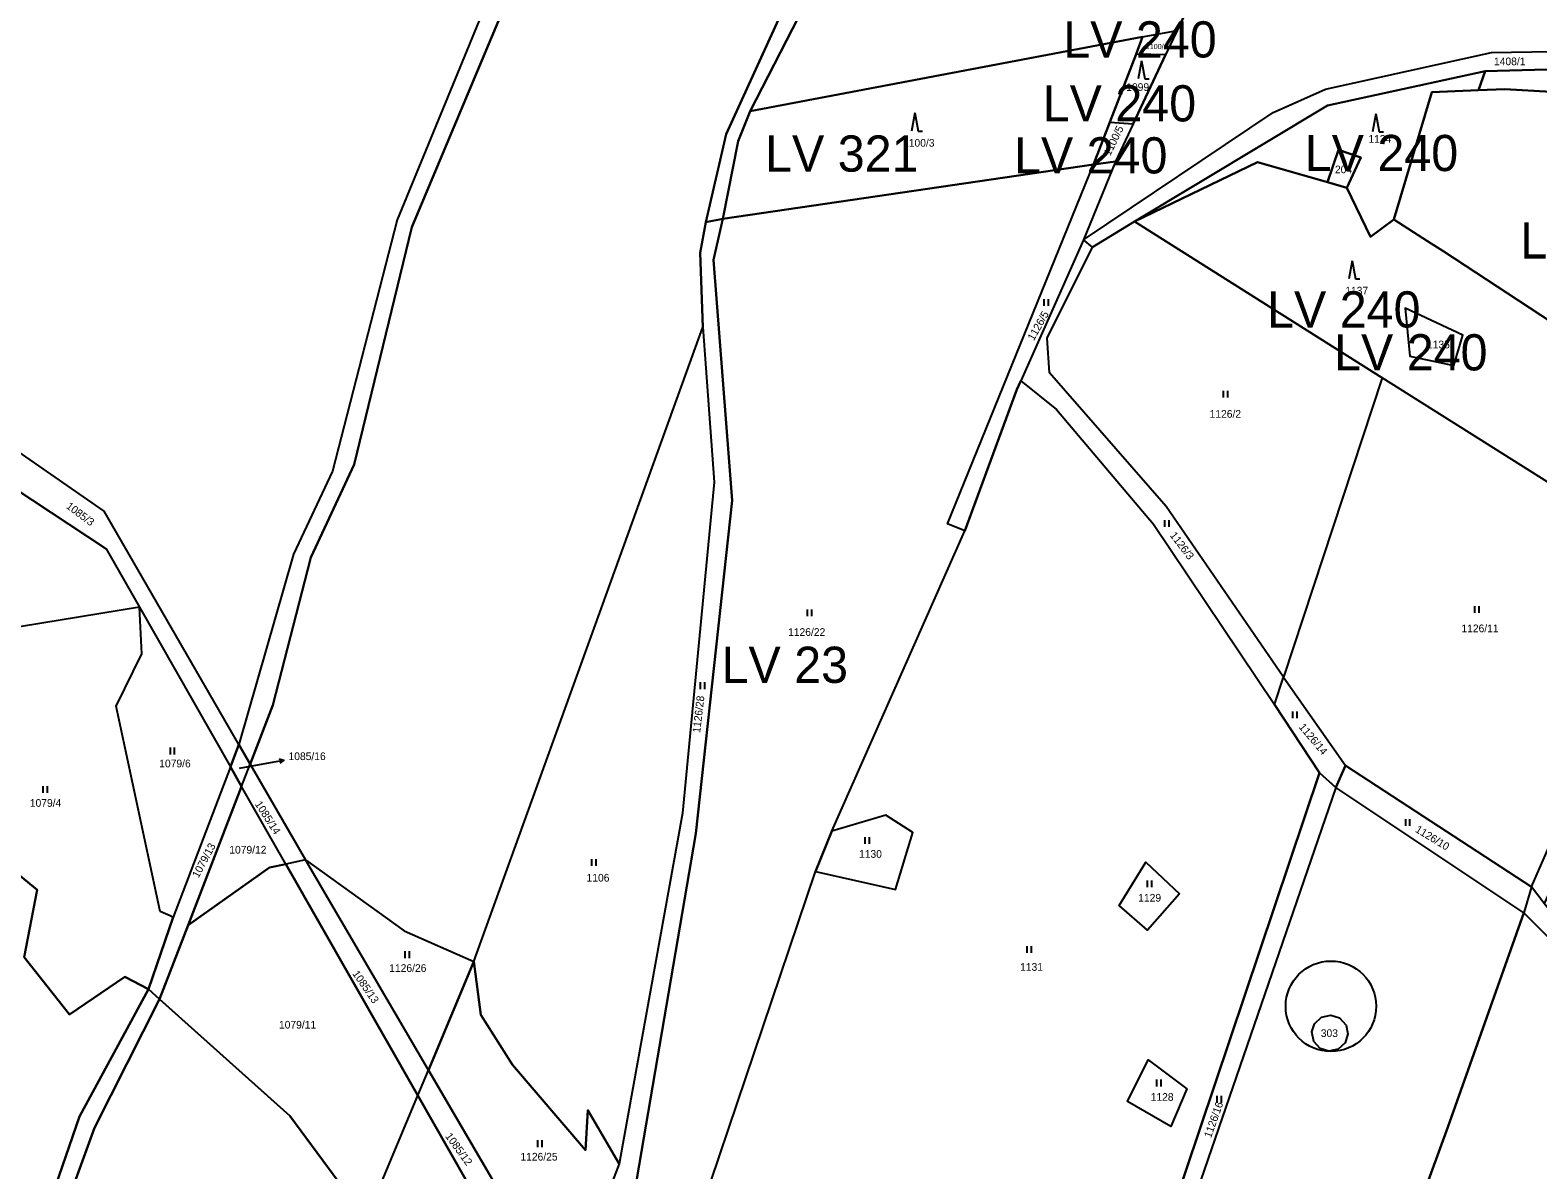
# Model space of a CAD drawing. Extents: x -588699 to -585793, y -1060280 to -1056731.
# Drawn here: x -587820.9 to -587487.8, y -1059020.2 to -1058768.4 of the extents above; entities that cross this region are included whole.
import ezdxf

# ---------------------------------------------------------------- set-up
doc = ezdxf.new("R2010")
doc.units = 0
for name, color, linetype in [('Druh pozemku', 7, 'Continuous'), ('Neřešené', 7, 'Continuous'), ('Parcela nároku', 7, 'Continuous'), ('Parcelní číslo', 7, 'Continuous'), ('Stavby', 7, 'Continuous'), ('Vnější obvod_převzatý', 7, 'Continuous')]:
    doc.layers.add(name, color=color, linetype=linetype)

msp = doc.modelspace()

# ---------------------------------------------------------------- linework, layer by layer
at = {"layer": 'Druh pozemku'}
for p, q in [((-587575.37, -1058775.14), (-587576.1, -1058779.14)), ((-587575.37, -1058775.14), (-587574.64, -1058779.14)), ((-587574.64, -1058779.14), (-587573.64, -1058779.14)), ((-587625.45, -1058786.65), (-587626.19, -1058790.65)), ((-587625.45, -1058786.65), (-587624.72, -1058790.65)), ((-587523.58, -1058786.82), (-587524.32, -1058790.82)), ((-587523.58, -1058786.82), (-587522.85, -1058790.82)), ((-587624.72, -1058790.65), (-587623.72, -1058790.65)), ((-587522.85, -1058790.82), (-587521.85, -1058790.82)), ((-587528.79, -1058819.3), (-587529.53, -1058823.3)), ((-587528.79, -1058819.3), (-587528.06, -1058823.3)), ((-587528.06, -1058823.3), (-587527.06, -1058823.3)), ((-587596.92, -1058827.76), (-587596.92, -1058829.26)), ((-587595.9, -1058829.26), (-587595.9, -1058827.76)), ((-587557.31, -1058848.04), (-587557.31, -1058849.54)), ((-587556.29, -1058849.54), (-587556.29, -1058848.04)), ((-587570.26, -1058876.6), (-587570.26, -1058878.1)), ((-587569.23, -1058878.1), (-587569.23, -1058876.6)), ((-587649.26, -1058896.35), (-587649.26, -1058897.85)), ((-587648.23, -1058897.85), (-587648.23, -1058896.35)), ((-587501.76, -1058895.62), (-587501.76, -1058897.12)), ((-587500.73, -1058897.12), (-587500.73, -1058895.62)), ((-587672.87, -1058912.44), (-587672.87, -1058913.94)), ((-587671.84, -1058913.94), (-587671.84, -1058912.44)), ((-587541.97, -1058918.91), (-587541.97, -1058920.41)), ((-587540.95, -1058920.41), (-587540.95, -1058918.91)), ((-587790.04, -1058926.89), (-587790.04, -1058928.39)), ((-587789.02, -1058928.39), (-587789.02, -1058926.89)), ((-587818.16, -1058935.4), (-587818.16, -1058936.9)), ((-587817.14, -1058936.9), (-587817.14, -1058935.4)), ((-587517.03, -1058942.67), (-587517.03, -1058944.17)), ((-587516.01, -1058944.17), (-587516.01, -1058942.67)), ((-587636.5, -1058946.64), (-587636.5, -1058948.14)), ((-587635.47, -1058948.14), (-587635.47, -1058946.64)), ((-587696.91, -1058951.53), (-587696.91, -1058953.03)), ((-587695.89, -1058953.03), (-587695.89, -1058951.53)), ((-587574.06, -1058956.22), (-587574.06, -1058957.72)), ((-587573.04, -1058957.72), (-587573.04, -1058956.22)), ((-587738.11, -1058971.88), (-587738.11, -1058973.38)), ((-587737.08, -1058973.38), (-587737.08, -1058971.88)), ((-587600.69, -1058970.74), (-587600.69, -1058972.24)), ((-587599.67, -1058972.24), (-587599.67, -1058970.74)), ((-587572.05, -1059000.24), (-587572.05, -1059001.74)), ((-587571.03, -1059001.74), (-587571.03, -1059000.24)), ((-587558.69, -1059003.84), (-587558.69, -1059005.34)), ((-587557.67, -1059005.34), (-587557.67, -1059003.84)), ((-587708.85, -1059013.64), (-587708.85, -1059015.14)), ((-587707.83, -1059015.14), (-587707.83, -1059013.64))]:
    msp.add_line(p, q, dxfattribs=at)
at = {"layer": 'Neřešené'}
msp.add_lwpolyline([(-587534.2, -1058801.97), (-587531.78, -1058794.81), (-587526.9, -1058796.47), (-587529.95, -1058803.18)], close=True, dxfattribs=at)
at = {"layer": 'Parcela nároku'}
for points in [[(-587647.07, -1058584.65), (-587664.66, -1058630.41), (-587683.23, -1058681.65), (-587693.72, -1058708.15), (-587714.84, -1058741.98), (-587721.68, -1058766.23), (-587739.86, -1058810.23), (-587754.13, -1058865.77), (-587762.73, -1058884.15), (-587774.83, -1058926.17), (-587772.32, -1058930.52), (-587767.29, -1058917.5), (-587758.89, -1058884.84), (-587749.31, -1058864.31), (-587736.6, -1058811.9), (-587717.44, -1058766.33), (-587711.58, -1058744.43), (-587689.88, -1058709.42), (-587678.89, -1058682.31), (-587662.12, -1058634.33), (-587639.34, -1058576.72)], [(-587639.34, -1058576.72), (-587662.12, -1058634.33), (-587678.89, -1058682.31), (-587689.88, -1058709.42), (-587711.58, -1058744.43), (-587717.44, -1058766.33), (-587736.6, -1058811.9), (-587749.31, -1058864.31), (-587758.89, -1058884.84), (-587767.29, -1058917.5), (-587772.32, -1058930.52), (-587760.08, -1058951.7), (-587738.27, -1058967.37), (-587722.9, -1058974.18), (-587672.29, -1058833.97), (-587672.88, -1058817.55), (-587671.61, -1058810.76), (-587667.13, -1058791.3), (-587654.74, -1058764.24), (-587629.6, -1058673.78), (-587614.6, -1058629.4), (-587607.6, -1058620.46), (-587591.67, -1058612.59)], [(-587647.07, -1058584.65), (-587664.66, -1058630.41), (-587683.23, -1058681.65), (-587693.72, -1058708.15), (-587714.84, -1058741.98), (-587721.68, -1058766.23), (-587739.86, -1058810.23), (-587754.13, -1058865.77), (-587762.73, -1058884.15), (-587774.83, -1058926.17), (-587804.58, -1058874.64), (-587847.22, -1058845.13)], [(-587591.67, -1058612.59), (-587607.6, -1058620.46), (-587614.6, -1058629.4), (-587629.6, -1058673.78), (-587654.74, -1058764.24), (-587667.13, -1058791.3), (-587671.61, -1058810.76), (-587667.89, -1058810.04), (-587664.46, -1058792.89), (-587661.81, -1058786.25), (-587651.11, -1058765.46), (-587635.03, -1058707.54), (-587611.6, -1058632.08), (-587605.95, -1058623.77), (-587550, -1058596.19)], [(-587503.55, -1058608.11), (-587519.89, -1058645.26), (-587523.16, -1058658.51), (-587545.16, -1058714.72), (-587549.47, -1058725.55), (-587557.48, -1058747.69), (-587567.46, -1058768.42), (-587570.01, -1058773.83), (-587577.2, -1058789.07), (-587581.11, -1058797.35), (-587588.18, -1058814.68), (-587546.21, -1058786.56), (-587534.66, -1058781.41), (-587498.02, -1058773.26), (-587471.36, -1058772.88)], [(-587518.99, -1059041.82), (-587507.67, -1059010.75), (-587490.84, -1058963.37), (-587532.39, -1058935.68), (-587573.18, -1059054.28)]]:
    msp.add_lwpolyline(points, dxfattribs=at)
for points in [[(-587555.44, -1058720.83), (-587567.98, -1058710.91), (-587568.51, -1058703.4), (-587557.67, -1058698.35), (-587557.12, -1058684.85), (-587563.12, -1058678.39), (-587554.81, -1058665.52), (-587552.28, -1058648.34), (-587544.06, -1058615.74), (-587541.88, -1058597.15), (-587538.61, -1058587.55), (-587540.61, -1058586.85), (-587550, -1058596.19), (-587605.95, -1058623.77), (-587611.6, -1058632.08), (-587635.03, -1058707.54), (-587651.11, -1058765.46), (-587661.81, -1058786.25), (-587575.09, -1058769.86), (-587567.46, -1058768.42), (-587557.48, -1058747.69), (-587549.47, -1058725.55)], [(-587575.09, -1058769.86), (-587567.46, -1058768.42), (-587570.01, -1058773.83), (-587576.54, -1058773.63)], [(-587664.46, -1058792.89), (-587667.89, -1058810.04), (-587585.95, -1058798.06), (-587582.34, -1058788.68), (-587576.54, -1058773.63), (-587575.09, -1058769.86), (-587661.81, -1058786.25)], [(-587498.02, -1058773.26), (-587471.36, -1058772.88), (-587419.8, -1058789.18), (-587416.34, -1058790.27), (-587417.7, -1058793.2), (-587474.82, -1058776.74), (-587499.41, -1058777.39), (-587534.25, -1058785.03), (-587576.88, -1058810.62), (-587586.16, -1058816.34), (-587588.18, -1058814.68), (-587546.21, -1058786.56), (-587534.66, -1058781.41)], [(-587570.01, -1058773.83), (-587576.54, -1058773.63), (-587582.34, -1058788.68), (-587577.2, -1058789.07)], [(-587529.95, -1058803.18), (-587526.9, -1058796.47), (-587531.78, -1058794.81), (-587534.2, -1058801.97), (-587549.72, -1058797.54), (-587576.88, -1058810.62), (-587534.25, -1058785.03), (-587499.41, -1058777.39), (-587500.85, -1058781.64), (-587511.16, -1058782.05), (-587519.56, -1058810.2), (-587524.77, -1058814)], [(-587474.82, -1058776.74), (-587417.7, -1058793.2), (-587419.85, -1058799.73), (-587474.59, -1058782.55), (-587495.05, -1058781.41), (-587500.85, -1058781.64), (-587499.41, -1058777.39)], [(-587500.85, -1058781.64), (-587495.05, -1058781.41), (-587474.59, -1058782.55), (-587419.85, -1058799.73), (-587427.49, -1058822.99), (-587444.5, -1058874.75), (-587454.12, -1058865.97), (-587468.24, -1058843.69), (-587508.54, -1058817.27), (-587512.1, -1058815), (-587519.56, -1058810.2), (-587511.16, -1058782.05)], [(-587585.95, -1058798.06), (-587582.34, -1058788.68), (-587577.2, -1058789.07), (-587581.11, -1058797.35)], [(-587526.9, -1058796.47), (-587531.78, -1058794.81), (-587534.2, -1058801.97), (-587529.95, -1058803.18)], [(-587614.37, -1058879.02), (-587618.23, -1058877.42), (-587585.95, -1058798.06), (-587667.89, -1058810.04), (-587669.95, -1058819.11), (-587665.84, -1058872.3), (-587673.86, -1058945.84), (-587688.37, -1059030.81), (-587675.13, -1059036.35), (-587674.36, -1059034.08), (-587647.4, -1058954.29), (-587643.79, -1058945.31)], [(-587618.23, -1058877.42), (-587585.95, -1058798.06), (-587581.11, -1058797.35), (-587588.18, -1058814.68), (-587602.04, -1058845.86), (-587602.88, -1058847.75), (-587614.37, -1058879.02)], [(-587534.2, -1058801.97), (-587529.95, -1058803.18), (-587524.77, -1058814), (-587519.56, -1058810.2), (-587512.1, -1058815), (-587508.54, -1058817.27), (-587468.24, -1058843.69), (-587454.12, -1058865.97), (-587444.5, -1058874.75), (-587452.08, -1058887.38), (-587453.2, -1058889.25), (-587460.84, -1058883.78), (-587522.15, -1058845.16), (-587576.88, -1058810.62), (-587549.72, -1058797.54)], [(-587690.75, -1059018.87), (-587698.16, -1059038), (-587707.95, -1059041.16), (-587706.25, -1059044.19), (-587694, -1059040.3), (-587688.37, -1059030.81), (-587673.86, -1058945.84), (-587665.84, -1058872.3), (-587669.95, -1058819.11), (-587667.89, -1058810.04), (-587671.61, -1058810.76), (-587672.88, -1058817.55), (-587672.29, -1058833.97), (-587669.75, -1058868.2), (-587676.79, -1058941.34)], [(-587576.88, -1058810.62), (-587522.15, -1058845.16), (-587543.94, -1058911.31), (-587569.92, -1058873.63), (-587595.65, -1058844.07), (-587596.19, -1058836.4), (-587586.16, -1058816.34)], [(-587595.65, -1058844.07), (-587596.19, -1058836.4), (-587586.16, -1058816.34), (-587588.18, -1058814.68), (-587602.04, -1058845.86), (-587594.1, -1058852.2), (-587572.66, -1058877.49), (-587545.94, -1058917.38), (-587543.94, -1058911.31), (-587569.92, -1058873.63)], [(-587504.3, -1058835.78), (-587517.1, -1058829.81), (-587516.07, -1058840.41), (-587506.34, -1058842.45)], [(-587506.34, -1058842.45), (-587504.3, -1058835.78), (-587517.1, -1058829.81), (-587516.07, -1058840.41)], [(-587722.9, -1058974.18), (-587672.29, -1058833.97), (-587669.75, -1058868.2), (-587676.79, -1058941.34), (-587690.75, -1059018.87), (-587697.72, -1059006.99), (-587698.19, -1059015.86), (-587714.35, -1058997), (-587721.32, -1058985.91)], [(-587804.58, -1058874.64), (-587847.22, -1058845.13), (-587849.15, -1058853.28), (-587804.12, -1058882.99), (-587796.78, -1058895.87), (-587776.67, -1058931.16), (-587774.83, -1058926.17)], [(-587522.15, -1058845.16), (-587543.94, -1058911.31), (-587530.26, -1058930.8), (-587489.18, -1058957.68), (-587475.53, -1058926.48), (-587453.2, -1058889.25), (-587460.84, -1058883.78)], [(-587674.36, -1059034.08), (-587647.4, -1058954.29), (-587629.69, -1058958.27), (-587625.89, -1058945.64), (-587631.81, -1058941.84), (-587643.79, -1058945.31), (-587614.37, -1058879.02), (-587602.88, -1058847.75), (-587602.04, -1058845.86), (-587594.1, -1058852.2), (-587572.66, -1058877.49), (-587545.94, -1058917.38), (-587535.97, -1058932.43), (-587575.54, -1059050.24), (-587591.86, -1059081.91)], [(-587849.15, -1058853.28), (-587804.12, -1058882.99), (-587796.78, -1058895.87), (-587853.95, -1058905.21), (-587850.15, -1058857.49)], [(-587489.18, -1058957.68), (-587475.53, -1058926.48), (-587453.2, -1058889.25), (-587452.08, -1058887.38), (-587369.55, -1058918.49), (-587370.84, -1058920.39), (-587450.19, -1058890.89), (-587470.98, -1058927.74), (-587486.32, -1058961.34)], [(-587789.32, -1058964.36), (-587792.22, -1058963.13), (-587801.94, -1058917.76), (-587796.24, -1058906.14), (-587796.78, -1058895.87), (-587853.95, -1058905.21), (-587857.94, -1058935.91), (-587833.41, -1058946.87), (-587819.38, -1058958.28), (-587822.27, -1058973.22), (-587812.23, -1058985.89), (-587800.01, -1058977.56), (-587794.76, -1058980.28)], [(-587801.94, -1058917.76), (-587796.24, -1058906.14), (-587796.78, -1058895.87), (-587776.67, -1058931.16), (-587789.32, -1058964.36), (-587792.22, -1058963.13)], [(-587545.94, -1058917.38), (-587543.94, -1058911.31), (-587530.26, -1058930.8), (-587532.39, -1058935.68), (-587535.97, -1058932.43)], [(-587772.32, -1058930.52), (-587774.83, -1058926.17), (-587776.67, -1058931.16), (-587774.22, -1058935.45)], [(-587774.22, -1058935.45), (-587776.67, -1058931.16), (-587789.32, -1058964.36), (-587794.76, -1058980.28), (-587792.35, -1058982.44), (-587786.05, -1058966.12)], [(-587772.32, -1058930.52), (-587760.08, -1058951.7), (-587764.43, -1058952.63), (-587774.22, -1058935.45)], [(-587530.26, -1058930.8), (-587489.18, -1058957.68), (-587490.84, -1058963.37), (-587532.39, -1058935.68)], [(-587764.43, -1058952.63), (-587774.22, -1058935.45), (-587786.05, -1058966.12), (-587768.03, -1058953.4)], [(-587575.54, -1059050.24), (-587535.97, -1058932.43), (-587532.39, -1058935.68), (-587573.18, -1059054.28), (-587590.63, -1059087.48), (-587616.93, -1059124.37), (-587644.87, -1059155.11), (-587647.13, -1059151.05), (-587616.59, -1059120.33), (-587594.98, -1059087.97), (-587591.86, -1059081.91)], [(-587800.01, -1058977.56), (-587812.23, -1058985.89), (-587822.27, -1058973.22), (-587819.38, -1058958.28), (-587833.41, -1058946.87), (-587857.94, -1058935.91), (-587921.85, -1059031.04), (-587985.54, -1059125.5), (-587999.42, -1059164.21), (-587980.79, -1059164.61), (-587966.55, -1059169.47), (-587944.72, -1059179.02), (-587897.85, -1059200.19), (-587902.23, -1059213.76), (-587896.62, -1059200.63), (-587881.71, -1059163.96), (-587839.09, -1059080.55), (-587819.95, -1059037.06), (-587810.06, -1059008.37), (-587794.76, -1058980.28)], [(-587625.89, -1058945.64), (-587631.81, -1058941.84), (-587643.79, -1058945.31), (-587647.4, -1058954.29), (-587629.69, -1058958.27)], [(-587732.93, -1058998.16), (-587760.08, -1058951.7), (-587764.43, -1058952.63), (-587735.27, -1059003.77)], [(-587738.27, -1058967.37), (-587722.9, -1058974.18), (-587732.93, -1058998.16), (-587760.08, -1058951.7)], [(-587574.42, -1058952.16), (-587566.95, -1058959.18), (-587573.98, -1058967.23), (-587580.29, -1058961.8)], [(-587573.98, -1058967.23), (-587580.29, -1058961.8), (-587574.42, -1058952.16), (-587566.95, -1058959.18)], [(-587735.27, -1059003.77), (-587764.43, -1058952.63), (-587768.03, -1058953.4), (-587786.05, -1058966.12), (-587792.35, -1058982.44), (-587763.53, -1059008.26), (-587746.69, -1059031.08)], [(-587479.58, -1058969.58), (-587486.32, -1058961.34), (-587489.18, -1058957.68), (-587490.84, -1058963.37), (-587483.48, -1058970.73), (-587480.52, -1058998.52), (-587467.05, -1059029.25), (-587466.55, -1059035.93), (-587447.41, -1059081.29), (-587445.39, -1059076.03), (-587462.84, -1059036.38), (-587465.03, -1059025.53), (-587477.12, -1058997.98)], [(-587507.67, -1059010.75), (-587518.99, -1059041.82), (-587509.34, -1059046.17), (-587512.35, -1059055.56), (-587522.91, -1059052.02), (-587539.49, -1059095.18), (-587562.32, -1059174.45), (-587544.58, -1059180.95), (-587489.61, -1059179.49), (-587482.72, -1059171.73), (-587447.41, -1059081.29), (-587466.55, -1059035.93), (-587467.05, -1059029.25), (-587480.52, -1058998.52), (-587483.48, -1058970.73), (-587490.84, -1058963.37)], [(-587714.35, -1058997), (-587698.19, -1059015.86), (-587697.72, -1059006.99), (-587690.75, -1059018.87), (-587698.16, -1059038), (-587707.95, -1059041.16), (-587711.65, -1059034.57), (-587715.11, -1059028.65), (-587732.93, -1058998.16), (-587722.9, -1058974.18), (-587721.32, -1058985.91)], [(-587792.35, -1058982.44), (-587794.76, -1058980.28), (-587810.06, -1059008.37), (-587819.95, -1059037.06), (-587839.09, -1059080.55), (-587881.71, -1059163.96), (-587896.62, -1059200.63), (-587893.09, -1059201.89), (-587878.87, -1059167.56), (-587835.47, -1059082.69), (-587818.85, -1059044.36), (-587806.74, -1059010.91)], [(-587746.69, -1059031.08), (-587763.53, -1059008.26), (-587792.35, -1058982.44), (-587806.74, -1059010.91), (-587818.85, -1059044.36), (-587835.47, -1059082.69), (-587878.87, -1059167.56), (-587893.09, -1059201.89), (-587865.33, -1059212.23), (-587860.66, -1059207.91), (-587828.89, -1059178.55), (-587808.03, -1059147.17), (-587791.1, -1059131.22), (-587781.05, -1059116.53)], [(-587529.73, -1058990.15), (-587530.36, -1058992.12), (-587531.9, -1058993.5), (-587533.91, -1058993.95), (-587535.89, -1058993.34), (-587537.28, -1058991.8), (-587537.71, -1058989.72), (-587537.13, -1058987.92), (-587535.56, -1058986.45), (-587533.53, -1058986), (-587531.56, -1058986.62), (-587530.14, -1058988.2)], [(-587530.14, -1058988.2), (-587529.73, -1058990.15), (-587530.36, -1058992.12), (-587531.9, -1058993.5), (-587533.91, -1058993.95), (-587535.89, -1058993.34), (-587537.28, -1058991.8), (-587537.71, -1058989.72), (-587537.13, -1058987.92), (-587535.56, -1058986.45), (-587533.53, -1058986), (-587531.56, -1058986.62)], [(-587732.93, -1058998.16), (-587715.11, -1059028.65), (-587720.84, -1059029.09), (-587735.27, -1059003.77)], [(-587578.43, -1059005.05), (-587573.85, -1058995.88), (-587565.36, -1059002.25), (-587568.83, -1059010.63)], [(-587565.36, -1059002.25), (-587568.83, -1059010.63), (-587578.43, -1059005.05), (-587573.85, -1058995.88)], [(-587746.69, -1059031.08), (-587735.27, -1059003.77), (-587720.84, -1059029.09)]]:
    msp.add_lwpolyline(points, close=True, dxfattribs=at)
at = {"layer": 'Parcelní číslo'}
for p, q in [((-587774.68, -1058931.44), (-587767.8, -1058930.18)), ((-587767.8, -1058930.18), (-587764.85, -1058929.64))]:
    msp.add_line(p, q, dxfattribs=at)
msp.add_lwpolyline([(-587765.92, -1058929.33), (-587764.85, -1058929.64), (-587765.74, -1058930.31)], dxfattribs=at)
at = {"layer": 'Stavby'}
msp.add_circle((-587533.48, -1058984.04), 10, dxfattribs=at)
at = {"layer": 'Vnější obvod_převzatý'}
for points in [[(-587661.81, -1058786.25), (-587575.09, -1058769.86), (-587576.54, -1058773.63), (-587582.34, -1058788.68), (-587585.95, -1058798.06), (-587667.89, -1058810.04)], [(-587661.81, -1058786.25), (-587664.46, -1058792.89), (-587667.89, -1058810.04)]]:
    msp.add_lwpolyline(points, dxfattribs=at)

# ---------------------------------------------------------------- texts
at = {"layer": 'Parcela nároku'}
for s, height, p in [('1100/4', 1.14, (-587574.38, -1058772.54)), ('1408/1', 1.7, (-587497.44, -1058776.1)), ('1099', 1.7, (-587578.72, -1058781.78)), ('1134', 1.7, (-587525.2, -1058793.24)), ('1100/3', 1.7, (-587628.04, -1058794.11)), ('204', 1.7, (-587532.59, -1058799.98)), ('1137', 1.7, (-587530.31, -1058826.76)), ('1135', 1.7, (-587512.25, -1058838.66)), ('1126/2', 1.7, (-587560.29, -1058854)), ('1126/22', 1.7, (-587653.45, -1058902.2)), ('1126/11', 1.7, (-587504.64, -1058901.39)), ('1079/6', 1.7, (-587792.42, -1058931.24)), ('1085/16', 0.1, (-587774.9, -1058931.44)), ('1079/4', 1.7, (-587821.02, -1058939.96)), ('1079/12', 1.7, (-587776.94, -1058950.3)), ('1130', 1.7, (-587637.77, -1058951.23)), ('1106', 1.7, (-587697.98, -1058956.49)), ('1129', 1.7, (-587576.07, -1058960.91)), ('1126/26', 1.7, (-587741.59, -1058976.45)), ('1131', 1.7, (-587602.17, -1058976.2)), ('1079/11', 1.7, (-587765.96, -1058988.97)), ('303', 1.7, (-587535.72, -1058990.83)), ('1128', 1.7, (-587573.31, -1059004.93)), ('1126/25', 1.7, (-587712.6, -1059018.13))]:
    msp.add_text(s, height=height, dxfattribs=at).set_placement(p)
for s, rotation, p in [('1100/5', 64.1799, (-587582.26, -1058796.26)), ('1126/5', 60.5233, (-587599.15, -1058837.1)), ('1085/3', 323.0128, (-587813.14, -1058873.84)), ('1126/3', 307.4485, (-587569.17, -1058880.01)), ('1126/28', 83.3498, (-587672.88, -1058923.68)), ('1126/14', 310.0253, (-587540.67, -1058922.4)), ('1085/14', 302.7321, (-587771.36, -1058939.35)), ('1126/10', 328.6697, (-587514.99, -1058945.41)), ('1079/13', 62.0357, (-587783.74, -1058955.81)), ('1085/13', 304.6832, (-587749.82, -1058976.84)), ('1126/16', 70.4601, (-587559.99, -1059013.25)), ('1085/12', 306.0889, (-587729.31, -1059012.77))]:
    msp.add_text(s, height=1.7, rotation=rotation, dxfattribs=at).set_placement(p)
at = {"layer": 'Parcelní číslo'}
msp.add_text('1085/16', height=1.7, dxfattribs=at).set_placement((-587763.85, -1058929.64))
at = {"layer": 'Vnější obvod_převzatý'}
for s, p in [('LV 240', (-587592.63, -1058774.4)), ('LV 240', (-587597.17, -1058788.52)), ('LV 321', (-587658.53, -1058799.62)), ('LV 240', (-587603.51, -1058800.02)), ('LV 240', (-587539.26, -1058799.5)), ('LV 240', (-587491.63, -1058818.81)), ('LV 240', (-587547.59, -1058834.06)), ('LV 240', (-587532.78, -1058843.54)), ('LV 23', (-587668.15, -1058912.58))]:
    msp.add_text(s, height=8, dxfattribs=at).set_placement(p)

doc.saveas('drawing.dxf')
